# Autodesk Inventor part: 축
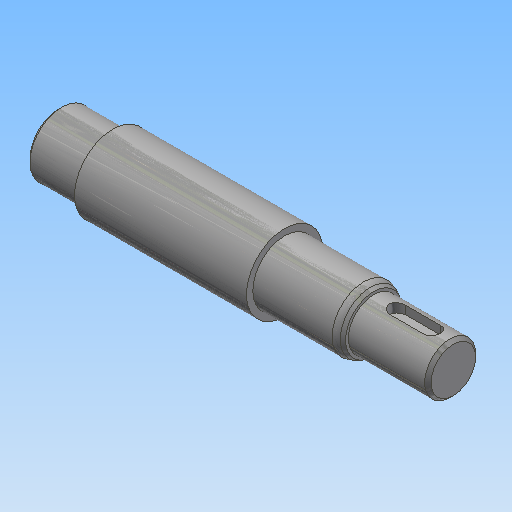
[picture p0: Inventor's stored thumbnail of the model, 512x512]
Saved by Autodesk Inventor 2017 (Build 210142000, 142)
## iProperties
Created: 2016-06
Part Number: 축
Material: 강철, 연강
Document SubType Name: Modeling
Designer: mduedu
Density: 7.86 g/cm^3
Appearance: 강철
Author: mduedu
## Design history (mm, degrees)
sketch "스케치1"
  geometry: L1 (-62, 0)-(62, 0); L2 (-62, 0)-(-62, 10); L3 (-62, 10)-(-45, 10); L4 (-45, 10)-(-45, 12); L5 (-45, 12)-(9, 12); L6 (9, 12)-(9, 10); L7 (9, 10)-(37, 10); L8 (37, 10)-(37, 8); L9 (37, 8)-(62, 8); L10 (62, 8)-(62, 0); 2 further points
  constraints: 20 end point, 5 parallel, 2 perpendicular, 1 coincident, 1 collinear, 1 horizontal, 1 midpoint, 1 vertical
  dimensions: "d0" = 124 distance of L1.start L1.end; "d2" = 16 diameter of L9 L1; "d3" = 20 diameter of L7 L1; "d4" = 24 diameter of L5 L1; "d5" = 20 diameter of L3 L1; "d6" = 17 distance of L2.end L3.end; "d7" = 25 distance of L8.end L9.end; "d8" = 53 distance from line of L5.end L10
revolve "회전1" sketch "스케치1" stored, may be unused: angle "d9" = 90 deg
chamfer "모따기1" distance "d10" = 2; stored, may be unused: second distance "d11" = 2, angle "d12" = 30 deg
fillet "모깎기1" dims "d13" = 4
node "작업 평면1"
sketch "스케치2"
  geometry: L1 (-5, 2.5)-(6, 2.5); L2 (6, -2.5)-(-5, -2.5); L3 (-5, 0)-(6, 0); L4 (-12.5, 8.845)-(-12.5, -8.845) reference; A1 r 2.5 centre (-5, 0) between (-5, 2.5) and (-5, -2.5); A2 r 2.5 centre (6, 0) between (6, -2.5) and (6, 2.5); 1 further point
  constraints: 6 end point, 4 point on circle, 3 tangent, 2 centre point, 2 parallel, 1 horizontal, 1 horizontal alignment
  dimensions: "d14" = 5 distance edge to line of A1 L4; "d15" = 5 distance between parallel lines of L2 L1; "d16" = 16 dimension on A2 A1
extrude "돌출1" cut sketch "스케치2" distance "d17" = 3; taper "d18" = 0 deg
chamfer "모따기2" distance "d19" = 1; stored, may be unused: second distance "d20" = 2, angle "d21" = 30 deg
sketch "스케치3"
  geometry: L1 (-37, -8)-(-61, -8) reference; L2 (-62, -7)-(-62, 7) reference; L3 (-38.5, -8)-(-40, -6.5); L4 (-40, -6.5)-(-40, -8); L5 (-38.5, -8)-(-40, -8); 1 further point
  constraints: 6 end point, 2 point on line, 1 collinear, 1 vertical
  dimensions: "d22" = 45 deg angle of L4 L3; "d23" = 22 distance between parallel lines of L2 L4; "d24" = 3 diameter of L3.start L4
revolve "회전2" stored, may be unused: angle "d25" = 90 deg
node "작업점1"
sketch "스케치4"
  geometry: 1 further point
hole "구멍1" sketch "스케치4" at (0, 0) diameter "d26" = 3.242; stored, may be unused: countersink angle "d30" = 90 deg, drill point angle "d32" = 120 deg; dims "d27" = 8, "d28" = 4, "d29" = 2, "d31" = 11
chamfer "모따기3" distance "d33" = 2; stored, may be unused: second distance "d34" = 2, angle "d35" = 30 deg
node "솔리드1"
pattern_circular "원형 패턴1" dims angle "d37" = 90 deg
node "작업점2"
